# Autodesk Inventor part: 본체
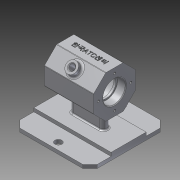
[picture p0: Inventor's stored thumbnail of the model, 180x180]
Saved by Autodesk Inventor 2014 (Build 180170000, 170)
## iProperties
Created: 2018-06
Part Number: 본체
Material: 알루미늄 6061
Document SubType Name: Modeling
Designer: geosung1
Density: 2.71 g/cm^3
Appearance: 알루미늄 - 평지
Mass: 554.042 g
Surface Area: 601.935 cm^2
Volume: 204.444 cm^3
Author: geosung1
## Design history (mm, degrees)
sketch "스케치1" dims "d0" = 60
  geometry: L1 (12.426, 30)-(30, 12.426); L2 (30, 12.426)-(30, -12.426); L3 (30, -12.426)-(12.426, -30); L4 (12.426, -30)-(-12.426, -30); L5 (-12.426, -30)-(-30, -12.426); L6 (-30, -12.426)-(-30, 12.426); L7 (-30, 12.426)-(-12.426, 30); L8 (-12.426, 30)-(12.426, 30); 4 further points
  constraints: 16 end point, 2 coincident, 2 vertical alignment, 1 midpoint, 19 other
extrude "돌출1" new body sketch "스케치1" stored distance "d1" = 70; taper "d2" = 0 deg
sketch "스케치2"
  geometry: L1 (-44.066, 0)-(44.066, 0); L2 (-35, -30)-(-35, 30) reference; L3 (-35, 30)-(35, 30) reference; L4 (35, 30)-(35, -30) reference; L5 (35, -30)-(-35, -30) reference; L6 (-35, 16)-(-23, 16); L7 (-23, 16)-(-23, 14); L8 (-23, 14)-(-20, 14); L9 (-20, 14)-(-20, 25); L10 (-20, 25)-(20, 25); L11 (20, 25)-(20, 14); L12 (20, 14)-(23, 14); L13 (23, 14)-(23, 16); L14 (23, 16)-(35, 16); L15 (-35, -30)-(-35, 30) reference; L16 (-35, 30)-(35, 30) reference; L17 (35, 30)-(35, -30) reference; L18 (35, -30)-(-35, -30) reference; L19 (-35, 16)-(-35, 0); L20 (35, 16)-(35, 0); L21 (-35, 0)-(35, 0); 2 further points
  constraints: 26 end point, 7 parallel, 4 equal length, 3 midpoint, 2 perpendicular, 2 point on line, 1 coincident, 1 collinear, 1 horizontal
  dimensions: "d3" = 28 diameter of L12 L1; "d4" = 32 diameter of L14 L1; "d5" = 50 diameter of L10 L1; "d6" = 12 distance of L6.start L6.end; "d7" = 3 distance of L7.end L8.end
revolve "회전1" sketch "스케치2" stored, may be unused: angle "d8" = 90 deg
sketch "스케치3" dims "d9" = 46
  geometry: C1 r 16 at (0, 0) reference; 2 further points
  constraints: 2 vertical alignment, 1 coincident, 2 other
hole "구멍1" sketch "스케치3" at (0, 23) diameter "d10" = 3.242; stored, may be unused: countersink angle "d14" = 90 deg, drill point angle "d16" = 118 deg; dims "d11" = 8, "d12" = 4, "d13" = 2, "d15" = 10
node "작업 평면1"
sketch "스케치4"
  geometry: L1 (-55, 55)-(55, 55); L2 (55, 55)-(55, -55); L3 (55, -55)-(-55, -55); L4 (-55, -55)-(-55, 55); L5 (-55, 55)-(55, -55); L6 (55, 55)-(-55, -55); 1 further point
  constraints: 12 end point, 2 midpoint, 2 parallel, 1 horizontal, 1 perpendicular
  dimensions: "d21" = 110 distance of L2.end L3.end; "d22" = 110 distance of L3.end L1.start
extrude "돌출2" join sketch "스케치4" distance "d23" = 5; taper "d24" = 0 deg
sketch "스케치5"
  geometry: L1 (-55, -55)-(55, -55) reference; L2 (55, 55)-(-55, 55) reference; L3 (-55, 55)-(-55, -55) reference; L4 (55, -25)-(-55, -25); L5 (-55, -25)-(-55, 25); L6 (-55, 25)-(55, 25); L7 (55, 25)-(55, -25); L8 (55, -25)-(-55, 25); L9 (-55, -25)-(55, 25); 1 further point
  constraints: 12 end point, 2 midpoint, 2 parallel, 1 horizontal, 1 perpendicular, 1 point on line
  dimensions: "d25" = 30 distance between parallel lines of L6 L2; "d26" = 30 distance between parallel lines of L1 L4 (derived)
extrude "돌출3" join sketch "스케치5" distance "d27" = 5; taper "d28" = 0 deg
sketch "스케치6"
  geometry: L1 (-55, -25)-(55, -25) reference; L2 (19, 0)-(-19, 0); L3 (19, -5)-(-19, -5); L4 (-19, 5)-(19, 5); A1 r 5 centre (19, 0) between (19, -5) and (19, 5); A2 r 5 centre (-19, 0) between (-19, 5) and (-19, -5); 2 further points
  constraints: 8 end point, 4 point on circle, 4 tangent, 2 centre point, 2 parallel, 1 coincident, 1 midpoint
  dimensions: "d29" = 5 radius of A1; "d30" = 38 distance of L2.start L2.end
extrude "돌출4" join sketch "스케치6" stored distance "d31" = 5; taper "d32" = 0 deg
sketch "스케치7"
  geometry: L1 (-55, -55)-(55, -55) reference; L2 (55, -55)-(55, -25) reference; C1 r 5 at (0, -45); 1 further point
  constraints: 1 centre point
  dimensions: "d33" = 55 distance from line of L2 C1.centre; "d34" = 10 distance from line of L1 C1.centre; "d35" = 10 diameter of C1
extrude "돌출5" cut sketch "스케치7" stored distance "d36" = 5; taper "d37" = 0 deg
sketch "스케치8"
  geometry: L1 (0, 0)-(0, 56.034); L2 (0, 0)-(26.163, 26.163); L3 (30, 12.426)-(12.426, 30) reference
  constraints: 4 end point, 1 vertical
  dimensions: "d38" = 45 deg angle of L1 L2; "d39" = 7 distance from line of L3 L2.end
node "작업 평면2"
sketch "스케치9"
  geometry: C1 r 8 at (0, 0); 1 further point
  constraints: 1 centre point, 1 coincident
  dimensions: "d40" = 16 diameter of C1
extrude "돌출6" join sketch "스케치9" stored distance "d41" = 5; taper "d42" = 0 deg
sketch "스케치10"
  geometry: C1 r 8 at (0, 0) reference; C2 r 4 at (0, 0)
  constraints: 1 centre point, 1 coincident
  dimensions: "d43" = 8 diameter of C2
extrude "돌출7" cut sketch "스케치10" distance "d44" = 30; taper "d45" = 0 deg
node "작업 평면3"
sketch "스케치11"
  geometry: L1 (-35, -30)-(35, -30) reference; L2 (35, 12.426)-(35, -12.426) reference; 2 further points
  constraints: 1 other
  dimensions: "d47" = 35 distance from line of L2 point (0, 0); "d48" = 30 distance from line of L1 point (0, 0)
feature "엠보싱1" sketch "스케치11" dims "d3" = 28, "d4" = 32, "d5" = 50, "d6" = 12, "d7" = 3, "d49" = 0.5, "d50" = 0
chamfer "모따기1" distance "d51" = 1; stored, may be unused: second distance "d52" = 2, angle "d53" = 45 deg
chamfer "모따기2" distance "d54" = 1; stored, may be unused: second distance "d55" = 2, angle "d56" = 45 deg
fillet "모깎기1" dims "d57" = 3
fillet "모깎기2" dims "d58" = 3
fillet "모깎기3" dims "d59" = 1
chamfer "모따기3" distance "d60" = 10; stored, may be unused: second distance "d61" = 2, angle "d62" = 45 deg
fillet "모깎기4" dims "d63" = 2
fillet "모깎기5" dims "d64" = 0.3
node "솔리드1"
pattern_circular "원형 패턴1" dims angle "d18" = 360 deg
mirror "대칭1"
mirror "대칭2"
node "절단 모서리 투영1"
node "절단 모서리 투영2"
other parameters: "d20" = -62, "d46" = 40.25
